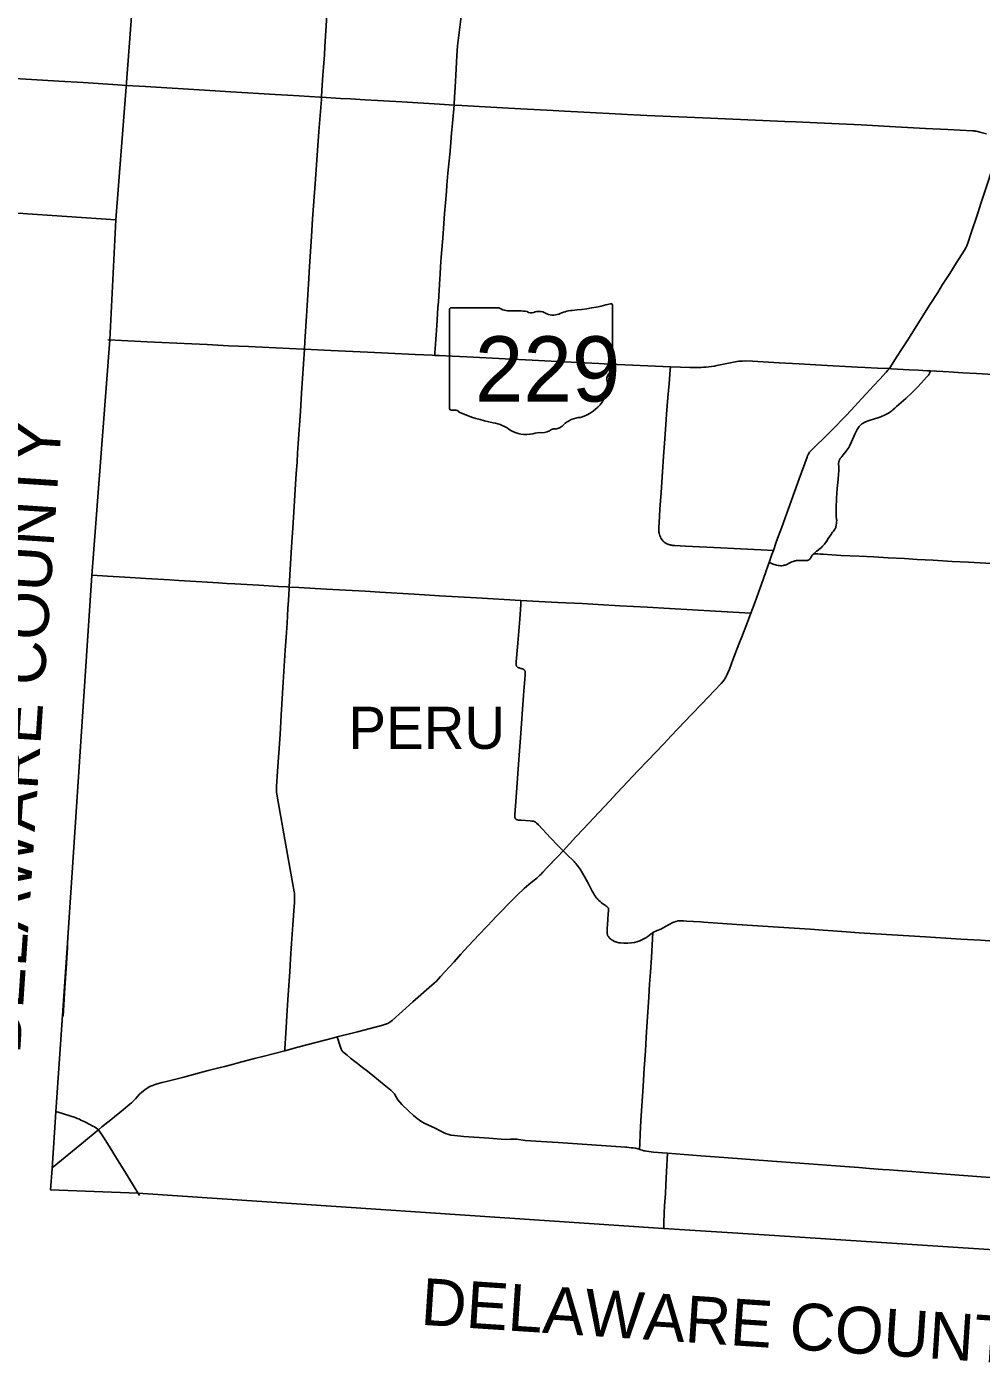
# Model space of a CAD drawing. Extents: x 1815539 to 1947826, y 273303 to 993194.
# Drawn here: x 1848246 to 1868609, y 855404 to 883973 of the extents above; entities that cross this region are included whole.
import ezdxf

# ---------------------------------------------------------------- set-up
doc = ezdxf.new("R2010")
doc.units = 0
for name, color, linetype in [('GM_X_Adjacent_County_Text', 7, 'Continuous'), ('GM_X_County', 7, 'Continuous'), ('GM_X_County_Road', 7, 'Continuous'), ('GM_X_State_Route', 7, 'Continuous'), ('GM_X_Township', 7, 'Continuous'), ('GM_X_Township_Road', 7, 'Continuous'), ('GM_X_Township_Text', 7, 'Continuous'), ('SC_Shading3', 7, 'Continuous')]:
    doc.layers.add(name, color=color, linetype=linetype)

msp = doc.modelspace()

# ---------------------------------------------------------------- linework, layer by layer
at = {"layer": 'GM_X_County'}
msp.add_lwpolyline([(1890695, 856480), (1886895, 856734), (1882352, 856998), (1879641, 857188), (1876143, 857428), (1873671, 857558), (1869100, 857855), (1863977, 858188), (1861827, 858324), (1850615, 859080), (1848752, 859146), (1848787, 859601), (1848864, 860810), (1849106, 864311), (1849634, 872258), (1850017, 877290), (1850147, 879854), (1845959, 880135)], dxfattribs=at)
at = {"layer": 'GM_X_County_Road'}
for points in [[(1866649, 876676), (1866673, 876713), (1866803, 876919), (1867040, 877293), (1867199, 877542), (1867365, 877805), (1867523, 878055), (1867681, 878305), (1867786, 878471), (1867936, 878706), (1868077, 878927), (1868253, 879204), (1868289, 879272), (1868302, 879298), (1868309, 879316), (1868322, 879354), (1868390, 879553), (1868526, 879975), (1868609, 880223), (1868720, 880567), (1868977, 881346), (1869055, 881586)], [(1853845, 872014), (1853859, 872274), (1853901, 872979), (1853919, 873274), (1853948, 873731), (1853964, 873978), (1853994, 874436), (1854011, 874682), (1854025, 874878), (1854038, 875075), (1854084, 875763), (1854110, 876156), (1854170, 877091)], [(1864174, 872796), (1864234, 872970), (1864284, 873109), (1864353, 873293), (1864625, 874049), (1864725, 874327), (1864892, 874790), (1864906, 874822), (1864914, 874839), (1864924, 874857), (1864935, 874876), (1864947, 874892), (1864960, 874910), (1864978, 874931), (1865366, 875308), (1865505, 875448), (1865642, 875589), (1865721, 875672), (1865832, 875793), (1866055, 876033), (1866155, 876142), (1866311, 876310), (1866444, 876455), (1866580, 876598), (1866619, 876641), (1866649, 876676)], [(1864084, 872541), (1864143, 872706), (1864174, 872796)], [(1863695, 871458), (1863764, 871641), (1863814, 871779), (1863864, 871918), (1863919, 872073), (1864005, 872320), (1864071, 872506), (1864084, 872541)], [(1853748, 862117), (1853750, 862165), (1853770, 862493), (1853801, 862984), (1853822, 863312), (1853856, 863803), (1853874, 864081), (1853894, 864409), (1853921, 864802), (1853950, 865195), (1853955, 865274), (1853961, 865391), (1853961, 865426), (1853960, 865457), (1853958, 865482), (1853954, 865506), (1853881, 865910), (1853831, 866184), (1853607, 867428), (1853581, 867590), (1853575, 867628), (1853573, 867652), (1853572, 867674), (1853571, 867703), (1853573, 867754), (1853594, 868081), (1853649, 868867), (1853675, 869277), (1853717, 869981), (1853760, 870669), (1853779, 870948), (1853798, 871242), (1853817, 871553), (1853828, 871734), (1853843, 871979), (1853845, 872014)], [(1859687, 866387), (1859824, 866534), (1859968, 866692), (1860116, 866845), (1860675, 867445), (1860843, 867625), (1861293, 868102), (1861498, 868315), (1861837, 868671), (1861996, 868837), (1862132, 868979), (1862437, 869300), (1862641, 869514), (1862923, 869812), (1863059, 869954), (1863111, 870016), (1863132, 870043), (1863148, 870070), (1863161, 870091), (1863176, 870121), (1863203, 870181), (1863235, 870263), (1863312, 870462), (1863441, 870798), (1863501, 870951), (1863602, 871211), (1863695, 871458)], [(1854870, 862411), (1855302, 862523), (1855842, 862663), (1855880, 862674), (1855903, 862682), (1855921, 862689), (1855948, 862702), (1855990, 862727), (1856042, 862766), (1856484, 863158), (1856890, 863515), (1856986, 863605), (1857032, 863653), (1857075, 863700), (1857361, 864017), (1857505, 864175), (1857669, 864358), (1857895, 864595), (1858054, 864761), (1858190, 864904), (1858262, 864979), (1858381, 865102), (1858508, 865235), (1858543, 865271), (1858599, 865329), (1858715, 865445), (1858861, 865577), (1858960, 865663), (1859073, 865757), (1859126, 865803), (1859182, 865855), (1859217, 865889), (1859254, 865927), (1859342, 866020), (1859567, 866259), (1859687, 866387)], [(1859687, 866387), (1859699, 866375), (1859714, 866360), (1859801, 866272), (1859881, 866197), (1859909, 866170), (1859925, 866154), (1859941, 866138), (1859949, 866128), (1859963, 866112), (1859984, 866085), (1860010, 866049), (1860049, 865995), (1860149, 865825), (1860221, 865697), (1860311, 865522), (1860337, 865477), (1860361, 865438), (1860380, 865408), (1860397, 865384), (1860414, 865363), (1860432, 865343), (1860449, 865327), (1860477, 865302), (1860502, 865281), (1860538, 865255), (1860568, 865234), (1860596, 865215), (1860609, 865206), (1860618, 865199), (1860621, 865197), (1860624, 865194), (1860626, 865192), (1860629, 865189), (1860635, 865184), (1860643, 865175), (1860645, 865172), (1860648, 865168), (1860650, 865165), (1860652, 865162), (1860654, 865157), (1860655, 865154), (1860655, 865151), (1860656, 865149), (1860656, 865146), (1860656, 865113), (1860655, 865093), (1860652, 865044), (1860644, 864918), (1860636, 864801), (1860631, 864730), (1860628, 864661), (1860628, 864646), (1860628, 864634), (1860629, 864625), (1860630, 864613), (1860632, 864604), (1860634, 864595), (1860639, 864580), (1860643, 864573), (1860649, 864562), (1860656, 864553), (1860665, 864539), (1860676, 864528), (1860687, 864516), (1860699, 864504), (1860711, 864494), (1860718, 864488), (1860726, 864482), (1860736, 864475), (1860748, 864468), (1860761, 864462), (1860772, 864457), (1860784, 864451), (1860794, 864447), (1860805, 864443), (1860816, 864440), (1860856, 864428), (1860878, 864423), (1860920, 864417), (1860985, 864412), (1861066, 864413), (1861147, 864419), (1861212, 864429), (1861260, 864440), (1861322, 864462), (1861381, 864489), (1861452, 864528), (1861493, 864555), (1861570, 864613), (1861586, 864625), (1861605, 864638)], [(1861605, 864638), (1861697, 864680), (1861770, 864715), (1861870, 864769), (1862028, 864852), (1862073, 864871), (1862095, 864878), (1862120, 864885), (1862130, 864888), (1862150, 864891), (1862162, 864892), (1862171, 864892), (1862183, 864892), (1862201, 864892), (1862224, 864891), (1862257, 864889), (1862318, 864885), (1862619, 864866), (1862686, 864861), (1863397, 864814), (1864619, 864733), (1864959, 864711), (1865239, 864692), (1865546, 864671), (1866005, 864637), (1866352, 864612), (1867418, 864549), (1868175, 864502), (1868595, 864476), (1869081, 864445)], [(1861321, 860011), (1861325, 860133), (1861334, 860346), (1861349, 860624), (1861394, 861360), (1861419, 861736), (1861443, 862112), (1861461, 862407), (1861483, 862734), (1861517, 863257), (1861535, 863535), (1861551, 863797), (1861571, 864108), (1861605, 864638)], [(1853748, 862117), (1854032, 862192), (1854794, 862391), (1854870, 862411)], [(1854870, 862411), (1854930, 862215), (1854953, 862153), (1854969, 862124), (1854990, 862097), (1855014, 862074), (1855078, 862023), (1855155, 861962), (1855244, 861890), (1855295, 861849), (1855346, 861809), (1855409, 861760), (1855512, 861679), (1855626, 861586), (1855869, 861391), (1856010, 861278), (1856058, 861234), (1856088, 861197), (1856114, 861156), (1856165, 861072), (1856203, 861019), (1856248, 860970), (1856391, 860834), (1856500, 860735), (1856576, 860672), (1856656, 860616), (1856726, 860573), (1856799, 860535), (1856962, 860461), (1857066, 860408)], [(1849777, 860431), (1849850, 860491), (1850041, 860645), (1850308, 860862), (1850446, 860977), (1850478, 861005), (1850507, 861033), (1850563, 861092), (1850653, 861188), (1850701, 861232), (1850764, 861283), (1850793, 861303), (1850831, 861328), (1850859, 861344), (1850888, 861360), (1850911, 861370), (1850947, 861385), (1850983, 861397), (1851025, 861410), (1851135, 861438), (1851230, 861461), (1851339, 861488), (1851596, 861554), (1851929, 861642), (1852119, 861692), (1852230, 861721), (1852373, 861757), (1852468, 861781), (1852658, 861831), (1852753, 861857), (1852943, 861907), (1853101, 861949), (1853307, 862004), (1853748, 862117)], [(1849777, 860431), (1849754, 860451), (1849720, 860474), (1849689, 860493), (1849656, 860510), (1849607, 860535), (1849471, 860606), (1849401, 860638), (1849367, 860654), (1849322, 860671), (1849275, 860689), (1848916, 860807), (1848869, 860822)], [(1848788, 859619), (1848989, 859783), (1849459, 860167), (1849749, 860407), (1849777, 860431)], [(1850650, 859027), (1850535, 859215), (1850337, 859536), (1850215, 859731), (1849965, 860136), (1849853, 860312), (1849793, 860405), (1849777, 860431)], [(1857066, 860408), (1857107, 860387), (1857180, 860350), (1857227, 860333), (1857291, 860318), (1857373, 860306), (1857569, 860289), (1858109, 860249), (1858370, 860230), (1858486, 860226), (1858568, 860230), (1858649, 860232), (1858698, 860229), (1858876, 860203), (1859220, 860178), (1859580, 860155), (1860300, 860108), (1861020, 860059), (1861051, 860056)], [(1861051, 860056), (1861090, 860053), (1861142, 860048), (1861186, 860042), (1861231, 860034), (1861310, 860014), (1861321, 860011)], [(1861321, 860011), (1861372, 859994), (1861409, 859984), (1861436, 859978), (1861469, 859971), (1861517, 859963), (1861564, 859957), (1861615, 859951), (1861909, 859928), (1861916, 859928)], [(1861835, 858314), (1861835, 858351), (1861835, 858433), (1861846, 858662), (1861854, 858810), (1861870, 859072), (1861880, 859252), (1861895, 859531), (1861916, 859928)], [(1861916, 859928), (1862629, 859873), (1863120, 859837), (1864150, 859761), (1864739, 859716), (1865507, 859658), (1865802, 859636), (1865998, 859622), (1866227, 859604), (1866505, 859582), (1866652, 859574), (1866832, 859561), (1867127, 859537), (1867486, 859512), (1868517, 859434), (1869367, 859370), (1869425, 859366)]]:
    msp.add_lwpolyline(points, dxfattribs=at)
at = {"layer": 'GM_X_State_Route'}
for points in [[(1849978, 877293), (1850128, 877285), (1850816, 877251), (1851127, 877236), (1851766, 877203), (1852094, 877189), (1852553, 877166), (1852979, 877146), (1854142, 877092), (1854170, 877091), (1854732, 877063), (1855518, 877026), (1855813, 877013), (1856534, 876978), (1856719, 876970)], [(1856719, 876970), (1856895, 876961), (1856952, 876959), (1857042, 876955), (1857321, 876944), (1857632, 876927), (1858451, 876887), (1859025, 876856), (1859434, 876835), (1859860, 876814), (1860450, 876786), (1860679, 876775), (1861499, 876738), (1861978, 876716), (1862196, 876705), (1862395, 876698), (1862473, 876700), (1862543, 876701), (1862632, 876704), (1862686, 876706), (1862740, 876711), (1862796, 876715), (1862854, 876723), (1862916, 876731), (1862968, 876741), (1863289, 876810), (1863401, 876830), (1863435, 876835), (1863483, 876838), (1863519, 876839), (1863581, 876840), (1863728, 876836), (1864301, 876803), (1864727, 876779), (1865071, 876758), (1865447, 876737), (1865710, 876723), (1865972, 876709), (1866135, 876700), (1866397, 876688), (1866649, 876676), (1866692, 876674), (1867069, 876653), (1867265, 876642), (1867462, 876632), (1867524, 876628), (1867920, 876607), (1868215, 876590), (1868509, 876574), (1868869, 876554)]]:
    msp.add_lwpolyline(points, dxfattribs=at)
at = {"layer": 'GM_X_Township'}
msp.add_lwpolyline([(1850147, 879854), (1850364, 882693), (1850523, 884772), (1850567, 885340), (1853740, 885139), (1854805, 885081), (1854864, 885092), (1854977, 885091), (1857606, 884909), (1869894, 884174), (1875339, 883824)], dxfattribs=at)
at = {"layer": 'GM_X_Township_Road'}
for points in [[(1857362, 882301), (1857363, 882321), (1857373, 882468), (1857386, 882681), (1857401, 882943), (1857416, 883221), (1857424, 883352), (1857438, 883564), (1857448, 883679), (1857475, 883906), (1857504, 884134), (1857525, 884296), (1857566, 884572), (1857602, 884782), (1857626, 884922)], [(1854564, 882939), (1854575, 883110), (1854595, 883371), (1854607, 883551), (1854649, 884223)], [(1846329, 882975), (1846570, 882962), (1846766, 882949), (1846979, 882935), (1847225, 882921), (1847421, 882907), (1848109, 882864), (1848927, 882815), (1849451, 882781), (1850188, 882733), (1850370, 882722)], [(1854534, 882470), (1854543, 882619), (1854564, 882939)], [(1850370, 882722), (1850779, 882696), (1852040, 882618), (1852597, 882587), (1853546, 882529), (1853808, 882514), (1854054, 882500), (1854496, 882472), (1854534, 882470)], [(1854170, 877091), (1854181, 877254), (1854216, 877794), (1854258, 878481), (1854281, 878858), (1854321, 879496), (1854345, 879872), (1854397, 880624), (1854480, 881736), (1854531, 882423), (1854534, 882470)], [(1854534, 882470), (1854938, 882445), (1855151, 882434), (1855462, 882417), (1856248, 882369), (1857050, 882321), (1857362, 882301)], [(1856952, 876959), (1856952, 876988), (1856953, 877021), (1856958, 877103), (1856977, 877398), (1856991, 877595), (1857018, 877972), (1857027, 878102), (1857044, 878348), (1857056, 878594), (1857063, 878692), (1857076, 878856), (1857090, 879053), (1857102, 879216), (1857113, 879380), (1857119, 879462), (1857141, 879772), (1857157, 879985), (1857176, 880214), (1857198, 880459), (1857208, 880590), (1857232, 880852), (1857251, 881048), (1857269, 881244), (1857284, 881408), (1857308, 881702), (1857328, 881915), (1857362, 882301)], [(1857362, 882301), (1857525, 882291), (1858393, 882241), (1858786, 882221), (1859474, 882186), (1859720, 882174), (1860130, 882154), (1860392, 882138), (1860670, 882122), (1861063, 882102), (1861476, 882083), (1862156, 882051), (1862833, 882020), (1863947, 881970), (1864422, 881951), (1864652, 881943), (1865111, 881920), (1865733, 881891), (1866045, 881878), (1866651, 881845), (1867421, 881803), (1867896, 881778), (1868420, 881752), (1868457, 881749), (1868479, 881746), (1868502, 881743), (1868534, 881737), (1868582, 881726), (1868724, 881687)], [(1861978, 876716), (1861973, 876651), (1861951, 876356), (1861926, 876062), (1861895, 875703), (1861878, 875474), (1861851, 875082), (1861831, 874804), (1861808, 874477), (1861779, 874036), (1861755, 873678), (1861736, 873382), (1861732, 873295), (1861731, 873269), (1861731, 873228), (1861732, 873201), (1861734, 873185), (1861737, 873161), (1861742, 873137), (1861753, 873105), (1861763, 873084), (1861774, 873061), (1861801, 873019), (1861815, 873003), (1861834, 872983), (1861847, 872972), (1861861, 872962), (1861889, 872946), (1861922, 872930), (1861941, 872923), (1861963, 872916), (1861975, 872913), (1861990, 872909), (1862007, 872906), (1862029, 872903), (1862047, 872901), (1862074, 872899), (1862303, 872887), (1863055, 872851), (1863332, 872839), (1863762, 872816), (1863917, 872809), (1864174, 872796)], [(1865034, 872721), (1865040, 872728), (1865044, 872733), (1865049, 872737), (1865066, 872753), (1865079, 872764), (1865093, 872777), (1865109, 872789), (1865174, 872839), (1865198, 872860), (1865222, 872884), (1865243, 872907), (1865265, 872933), (1865283, 872954), (1865305, 872985), (1865345, 873049), (1865397, 873128), (1865414, 873153), (1865423, 873167), (1865435, 873183), (1865448, 873199), (1865458, 873210), (1865472, 873228), (1865486, 873249), (1865495, 873263), (1865499, 873274), (1865504, 873285), (1865509, 873301), (1865516, 873333), (1865523, 873382), (1865524, 873405), (1865525, 873436), (1865523, 873458), (1865517, 873534), (1865516, 873549), (1865515, 873562), (1865514, 873600), (1865515, 873660), (1865517, 873775), (1865519, 873832), (1865520, 873872), (1865522, 873911), (1865529, 874019), (1865537, 874117), (1865549, 874248), (1865562, 874410), (1865569, 874512), (1865570, 874536), (1865569, 874565), (1865568, 874590), (1865566, 874639), (1865566, 874653), (1865567, 874665), (1865568, 874674), (1865569, 874684), (1865572, 874694), (1865576, 874708), (1865579, 874716), (1865582, 874724), (1865586, 874732), (1865594, 874745), (1865602, 874756), (1865610, 874768), (1865621, 874783), (1865665, 874836), (1865728, 874912), (1865765, 874966), (1865782, 874994), (1865797, 875023), (1865839, 875112), (1865912, 875277), (1865964, 875379), (1865978, 875401), (1865990, 875420), (1866007, 875440), (1866021, 875457), (1866038, 875474), (1866057, 875490), (1866075, 875503), (1866093, 875513), (1866114, 875525), (1866142, 875538), (1866218, 875566), (1866421, 875631), (1866465, 875646), (1866498, 875660), (1866528, 875674), (1866557, 875689), (1866590, 875707), (1866628, 875729), (1866681, 875764), (1866701, 875779), (1866726, 875799), (1866767, 875836), (1866804, 875870), (1867002, 876042), (1867135, 876164), (1867251, 876280), (1867329, 876364), (1867444, 876491), (1867485, 876539), (1867492, 876548), (1867499, 876559), (1867503, 876566), (1867508, 876579), (1867513, 876592), (1867519, 876609), (1867524, 876628)], [(1864084, 872541), (1864126, 872521), (1864145, 872513), (1864157, 872508), (1864172, 872502), (1864194, 872495), (1864217, 872489), (1864241, 872483), (1864274, 872475), (1864300, 872472), (1864324, 872470), (1864350, 872470), (1864374, 872472), (1864391, 872475), (1864406, 872478), (1864425, 872484), (1864446, 872491), (1864475, 872505), (1864498, 872517), (1864571, 872554), (1864594, 872562), (1864616, 872570), (1864634, 872574), (1864650, 872577), (1864668, 872579), (1864687, 872581), (1864699, 872583), (1864713, 872583), (1864730, 872584), (1864745, 872584), (1864762, 872583), (1864785, 872582), (1864810, 872580), (1864847, 872578), (1864859, 872578), (1864877, 872579), (1864890, 872580), (1864899, 872582), (1864906, 872583), (1864915, 872586), (1864922, 872590), (1864929, 872593), (1864936, 872598), (1864942, 872603), (1864949, 872610), (1864959, 872622), (1864964, 872630), (1864971, 872641), (1864981, 872658), (1864988, 872670), (1864996, 872683), (1865003, 872693), (1865010, 872701), (1865016, 872707), (1865020, 872711), (1865023, 872713), (1865029, 872718), (1865034, 872721)], [(1865034, 872721), (1865039, 872722), (1865048, 872723), (1865057, 872724), (1865063, 872724), (1865074, 872724), (1865121, 872723), (1865174, 872719), (1865240, 872715), (1865615, 872691), (1866008, 872671), (1866318, 872656), (1866625, 872639), (1866969, 872621), (1867244, 872605), (1867583, 872585), (1867992, 872562), (1868336, 872544), (1868958, 872513), (1869318, 872493), (1870137, 872450)], [(1849640, 872268), (1849968, 872248), (1850335, 872225), (1850789, 872198), (1851300, 872168), (1851491, 872156), (1851979, 872125), (1852329, 872103), (1852512, 872093), (1852682, 872085), (1853195, 872053), (1853613, 872026), (1853809, 872016), (1853845, 872014)], [(1853845, 872014), (1854049, 872003), (1854396, 871983), (1854641, 871969), (1855465, 871923), (1855776, 871905), (1856514, 871862), (1856841, 871842), (1857054, 871829), (1857448, 871807), (1857841, 871786), (1858789, 871730)], [(1858789, 871730), (1858783, 871640), (1858763, 871326), (1858730, 870901), (1858694, 870493), (1858688, 870421), (1858687, 870408), (1858686, 870396), (1858685, 870386), (1858685, 870379), (1858685, 870373), (1858685, 870365), (1858685, 870359), (1858686, 870353), (1858687, 870348), (1858689, 870340), (1858692, 870333), (1858695, 870327), (1858700, 870320), (1858705, 870314), (1858710, 870309), (1858716, 870304), (1858722, 870300), (1858728, 870297), (1858734, 870294), (1858738, 870292), (1858746, 870289), (1858751, 870287), (1858763, 870284), (1858788, 870278), (1858802, 870274), (1858811, 870272), (1858816, 870270), (1858821, 870269), (1858826, 870267), (1858835, 870263), (1858838, 870261), (1858842, 870259), (1858846, 870256), (1858851, 870252), (1858856, 870247), (1858859, 870245), (1858862, 870242), (1858865, 870238), (1858868, 870234), (1858871, 870228), (1858873, 870224), (1858876, 870217), (1858879, 870209), (1858881, 870201), (1858881, 870195), (1858882, 870181), (1858882, 870154), (1858880, 870130), (1858846, 869708), (1858778, 868793), (1858757, 868515), (1858739, 868237), (1858709, 867828), (1858680, 867436), (1858659, 867161), (1858658, 867138), (1858657, 867122), (1858657, 867115), (1858657, 867107), (1858658, 867102), (1858660, 867095), (1858662, 867088), (1858665, 867080), (1858667, 867077), (1858669, 867073), (1858673, 867068), (1858678, 867063), (1858684, 867058), (1858690, 867054), (1858697, 867050), (1858704, 867048), (1858711, 867045), (1858719, 867043), (1858728, 867041), (1858733, 867040), (1858739, 867039), (1858753, 867038), (1858792, 867035), (1858989, 867023), (1859020, 867020), (1859040, 867018), (1859050, 867017), (1859064, 867014), (1859071, 867012), (1859077, 867009), (1859088, 867004), (1859097, 866998), (1859105, 866992), (1859115, 866985), (1859122, 866978), (1859162, 866939), (1859419, 866664), (1859579, 866501), (1859687, 866387)], [(1858789, 871730), (1859170, 871708), (1859574, 871685), (1860094, 871660), (1860433, 871642), (1860901, 871616), (1861484, 871584), (1861959, 871558), (1862940, 871500), (1863695, 871458)], [(1849021, 862856), (1849057, 863463), (1849090, 863978), (1849102, 864092), (1849117, 864321), (1849117, 864329), (1849117, 864338), (1849117, 864343), (1849117, 864351), (1849116, 864355), (1849116, 864358), (1849115, 864361), (1849113, 864368), (1849111, 864373), (1849108, 864379)]]:
    msp.add_lwpolyline(points, dxfattribs=at)
at = {"layer": 'SC_Shading3'}
for p, q in [((1857265, 877938), (1857265, 875825)), ((1858318, 877975), (1857299, 877975)), ((1860745, 876922), (1860745, 878027)), ((1860745, 876922), (1860745, 876922))]:
    msp.add_line(p, q, dxfattribs=at)
for centre, major_axis, start_param, end_param in [((1857305, 877943), (40.3, 0), 1.712693, 3.28349), ((1858561, 878220), (391, 0), 4.042523, 4.731795), ((1859505, 880856), (3691, 0), 4.814394, 5.042369), ((1860707, 878032), (38.7, 0), 6.141152, 7.989035), ((1858691, 876788), (1404, 0), 1.404758, 1.657858), ((1859009, 877954), (113, 0), 3.836095, 5.185415), ((1859175, 877710), (235, 0), 0.950623, 2.079405), ((1859478, 878045), (282, 0), 4.081561, 5.145723), ((1859976, 877329), (743, 0), 1.699011, 2.107814), ((1860736, 876841), (60, 0), 1.883978, 3.671073), ((1860355, 876701), (360, 0), 5.934695, 6.695948), ((1860704, 876917), (41.5, 0), 5.05454, 6.418171), ((1860884, 876459), (262, 0), 2.387724, 3.262537), ((1859712, 876318), (923, 0), 5.101752, 6.440018), ((1857305, 875821), (40.7, 0), 3.00124, 4.508301), ((1857311, 876037), (310, 0), 4.665946, 4.897461), ((1857375, 875703), (112, 0), 0.519207, 1.627899), ((1858788, 877602), (2665, 0), 4.195997, 4.488961), ((1857993, 874876), (834, 0), 0.823519, 1.323587), ((1858895, 875693), (529, 0), 4.026481, 4.996735), ((1859240, 875535), (282, 0), 4.691044, 5.507374), ((1859495, 875330), (79.4, 0), 1.147584, 2.315152), ((1859461, 875620), (298, 0), 4.937069, 5.64225), ((1860101, 875232), (506, 0), 1.647645, 2.488434), ((1859201, 874962), (435, 0), 1.495662, 1.94098)]:
    msp.add_ellipse(centre, major_axis=major_axis, ratio=0.8, start_param=start_param, end_param=end_param, dxfattribs=at)

# ---------------------------------------------------------------- texts
at = {"layer": 'GM_X_Adjacent_County_Text'}
for rotation, p in [(86.2231, (1848101, 862036)), (356.2231, (1856635, 856270))]:
    msp.add_text('DELAWARE COUNTY', height=1000, rotation=rotation, dxfattribs=at).set_placement(p)
at = {"layer": 'GM_X_Township_Text'}
msp.add_text('PERU', height=900, rotation=0, dxfattribs=at).set_placement((1855108, 868560))
at = {"layer": 'SC_Shading3'}
msp.add_text('229', height=1392.2, dxfattribs=at).set_placement((1857805, 875974))

doc.saveas('drawing.dxf')
